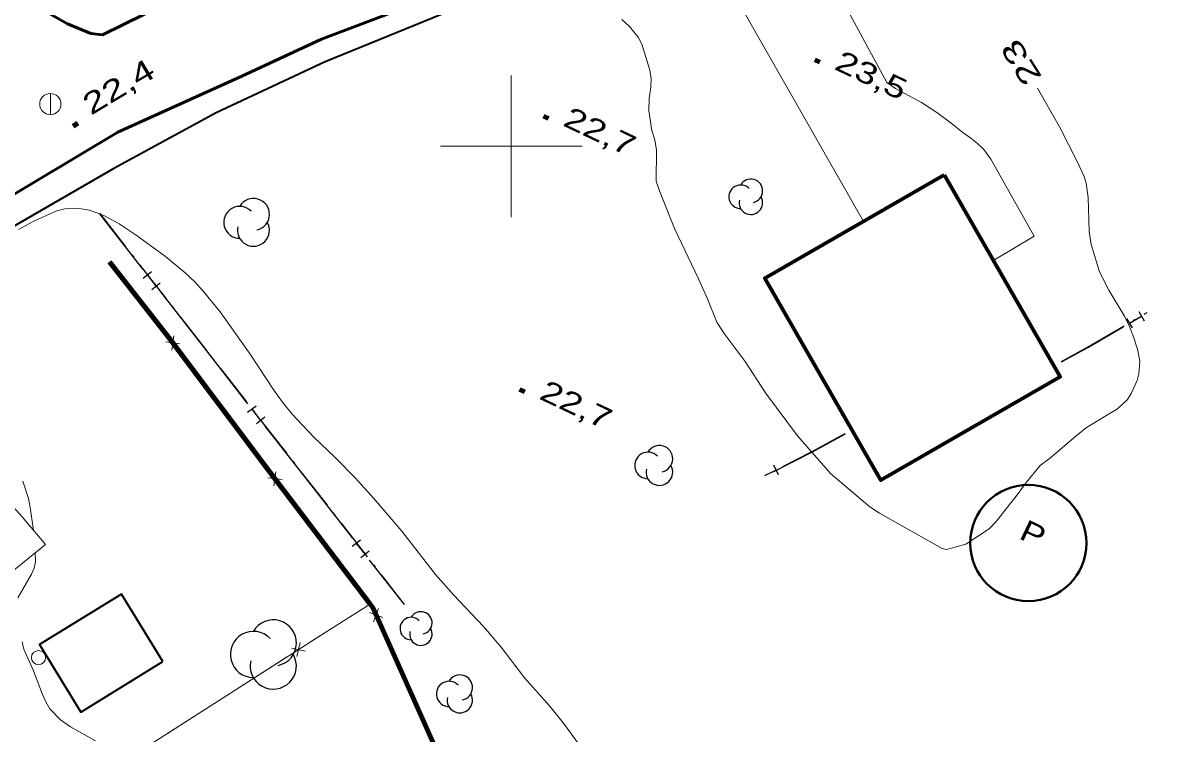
# Model space of a CAD drawing. Extents: x 356765 to 358572, y 5103174 to 5104650.
# Drawn here: x 357465.5 to 357547, y 5103858.5 to 5103908.7 of the extents above; entities that cross this region are included whole.
import ezdxf
from ezdxf.enums import TextEntityAlignment as Align

# ---------------------------------------------------------------- set-up
doc = ezdxf.new("R2010")
doc.units = 0
doc.header["$LTSCALE"] = 0.6
doc.linetypes.add('DOT_DASHED', pattern=[7.7, 5, -1.2, 0.3, -1.2])
for name, color, linetype, lineweight in [('19', 7, 'Continuous', 13), ('2', 7, 'Continuous', 13), ('21', 7, 'Continuous', 53), ('22', 7, 'Continuous', 35), ('3', 7, 'Continuous', 140), ('31', 7, 'Continuous', 70), ('36', 7, 'Continuous', 13), ('37', 7, 'Continuous', 13), ('38', 7, 'Continuous', 40), ('44', 7, 'Continuous', 25), ('61', 7, 'Continuous', 13)]:
    doc.layers.add(name, color=color, linetype=linetype, lineweight=lineweight)

msp = doc.modelspace()

# ---------------------------------------------------------------- linework, layer by layer
at = {"layer": '19'}
for p, q in [((357526.52, 5103904.49), (357519.66, 5103917.24)), ((357513.1, 5103915.34), (357524.85, 5103894.74))]:
    msp.add_line(p, q, dxfattribs=at)
for points in [[(357526.52, 5103904.49), (357527.12, 5103904.07), (357528.96, 5103903.09), (357530.04, 5103902.39), (357531.07, 5103901.62), (357531.89, 5103900.98), (357532.44, 5103900.57), (357532.92, 5103900.2), (357533.36, 5103899.77), (357533.87, 5103899.09), (357536.92, 5103893.64), (357534.13, 5103891.98)], [(357453.17, 5103887.5), (357465.48, 5103873.84), (357467.12, 5103871.87), (357464.62, 5103869.85), (357463.31, 5103871.23), (357454.95, 5103881.24), (357452.89, 5103883.17), (357451.37, 5103884.38), (357449.99, 5103885.55)]]:
    msp.add_lwpolyline(points, dxfattribs=at)
at = {"layer": '2'}
for points in [[(357507.82, 5103908.95), (357508.36, 5103908.45), (357508.96, 5103907.71), (357509.21, 5103907.21), (357509.79, 5103905.38), (357509.89, 5103904.78), (357509.86, 5103904.17), (357509.74, 5103903.37), (357509.71, 5103902.51), (357509.92, 5103901.12), (357510.13, 5103900.45), (357510.25, 5103899.73), (357510.24, 5103897.53), (357510.46, 5103896.84), (357511.53, 5103894.19), (357513.23, 5103890.63), (357513.83, 5103889.28), (357514.51, 5103887.58), (357515.03, 5103886.78), (357516.52, 5103884.79), (357517.96, 5103882.59), (357520.22, 5103879.55), (357522.57, 5103876.86), (357525.31, 5103874.54), (357526, 5103874.09), (357530.42, 5103871.59), (357530.74, 5103871.53), (357532.1, 5103871.91), (357533.74, 5103872.99), (357534.26, 5103873.53), (357535.73, 5103875.38), (357536.38, 5103876.29), (357537.34, 5103877.46), (357537.97, 5103877.93), (357539.85, 5103879.54), (357540.62, 5103880.13), (357542.8, 5103881.46), (357543.5, 5103882.12), (357543.76, 5103882.53), (357544.19, 5103883.47), (357544.31, 5103883.94), (357544.37, 5103884.83), (357544.21, 5103885.68), (357543.96, 5103886.47), (357543.66, 5103887.26), (357543.29, 5103888.01), (357542.2, 5103889.84), (357541.53, 5103891.12), (357540.95, 5103893.05), (357540.81, 5103893.98), (357540.74, 5103896.38), (357540.6, 5103897.38), (357540.44, 5103897.86), (357540, 5103898.83), (357538.69, 5103901.41), (357537.15, 5103904.11)], [(357505.79, 5103856.38), (357503.75, 5103859.17), (357502.71, 5103860.5), (357500.94, 5103862.46), (357499.28, 5103864.62), (357498.04, 5103866.09), (357495.95, 5103868.3), (357494.66, 5103869.76), (357492.27, 5103872.82), (357490.3, 5103875.12), (357488.99, 5103876.58), (357487.56, 5103878.03), (357486.04, 5103879.48), (357484.53, 5103881.08), (357483.84, 5103881.93), (357483.23, 5103882.78), (357481.62, 5103885.25), (357479.44, 5103888.3), (357478.25, 5103889.76), (357477.65, 5103890.43), (357476.99, 5103891.05), (357475.59, 5103892.22), (357473.53, 5103893.73), (357472.33, 5103894.53), (357471.29, 5103895.08), (357470.74, 5103895.3), (357470.19, 5103895.48), (357469.63, 5103895.58), (357469.07, 5103895.63), (357468.49, 5103895.59), (357467.93, 5103895.44), (357467.37, 5103895.21), (357466.25, 5103894.68), (357465.21, 5103894.12)], [(357465.51, 5103876.34), (357465.91, 5103875.13), (357466.04, 5103874.5), (357466.28, 5103872.88)], [(357466.4, 5103871.29), (357466.41, 5103870.65), (357466.31, 5103870.22), (357466.12, 5103869.78), (357465.16, 5103868.11)], [(357465.48, 5103865), (357465.6, 5103864.49), (357466.27, 5103862.96), (357466.9, 5103861.3), (357467.13, 5103860.78), (357467.42, 5103860.28), (357468.17, 5103859.51), (357468.88, 5103859.01), (357470.64, 5103858.01)]]:
    msp.add_lwpolyline(points, dxfattribs=at)
at = {"layer": '21'}
for points in [[(357471.14, 5103907.86), (357470.33, 5103907.97), (357468.68, 5103908.63), (357466.84, 5103909.68), (357464.76, 5103911.63), (357462.43, 5103913.84), (357445.34, 5103929.7), (357443.26, 5103931.71), (357439.31, 5103935.34), (357435.21, 5103939.42), (357431.12, 5103943.34), (357426.66, 5103947.84), (357421.28, 5103952.59), (357416.19, 5103957.55), (357411.47, 5103962.13), (357406.99, 5103966.4)], [(357651.76, 5103955.95), (357619.95, 5103948.59), (357588.58, 5103941.73), (357566.37, 5103936.76), (357548.68, 5103932.92), (357532.03, 5103928.56), (357530.85, 5103928.26), (357513.75, 5103924.04), (357511.54, 5103923.43), (357501.65, 5103920.72), (357490.41, 5103916.62), (357474.1, 5103909.32), (357471.14, 5103907.86)], [(357678.36, 5103954.94), (357640.5, 5103946.09), (357619.43, 5103941.41), (357599.16, 5103936.98), (357552.82, 5103926.37), (357536.94, 5103922.93), (357520.26, 5103918.95), (357503.82, 5103914.09), (357486.6, 5103907.55), (357480.97, 5103904.95), (357472.22, 5103900.99), (357457.26, 5103892.04), (357451.72, 5103889.03), (357438.42, 5103880.3), (357419.6, 5103867.79), (357409.99, 5103860.91), (357402.64, 5103855.12), (357395.85, 5103849.3), (357387.1, 5103841.32), (357379.78, 5103834.37), (357370.08, 5103824.18), (357363.77, 5103817.05), (357355.31, 5103807.73), (357353.75, 5103805.99)]]:
    msp.add_lwpolyline(points, dxfattribs=at)
at = {"layer": '22'}
msp.add_lwpolyline([(357647.75, 5103946.51), (357634.21, 5103943.46), (357622.47, 5103940.88), (357609.15, 5103938.01), (357596.04, 5103935), (357584.77, 5103932.34), (357572.98, 5103929.8), (357562.05, 5103927.46), (357547.85, 5103924.19), (357536.87, 5103921.73), (357525.36, 5103918.83), (357514.86, 5103915.9), (357504.84, 5103912.75), (357495.77, 5103909.59), (357486.87, 5103905.97), (357479.16, 5103902.36), (357471.94, 5103898.43), (357462.55, 5103893.01), (357451.44, 5103886.54), (357441.53, 5103880.61), (357430.12, 5103873.12), (357417.36, 5103864.38), (357407.44, 5103856.91)], dxfattribs=at)
at = {"layer": '3'}
for p, q in [((357521.43, 5103906.1), (357521.79, 5103905.93)), ((357502.27, 5103902.12), (357502.63, 5103901.95)), ((357469.06, 5103901.41), (357469.4, 5103901.62)), ((357500.59, 5103882.83), (357500.95, 5103882.66))]:
    msp.add_line(p, q, dxfattribs=at)
at = {"layer": '31'}
msp.add_lwpolyline([(357530.57, 5103897.97), (357538.76, 5103883.71), (357526.09, 5103876.43), (357517.9, 5103890.69), (357530.57, 5103897.97)], close=True, dxfattribs=at)
at = {"layer": '31', "lineweight": 35}
msp.add_lwpolyline([(357475.41, 5103863.62), (357472.49, 5103868.38), (357466.7, 5103864.82), (357469.62, 5103860.05), (357475.41, 5103863.62)], close=True, dxfattribs=at)
at = {"layer": '36'}
msp.add_line((357467.46, 5103902.21), (357467.46, 5103903.71), dxfattribs=at)
for centre, radius in [((357467.4575, 5103902.9723), 0.75), ((357466.6238, 5103863.8971), 0.5)]:
    msp.add_circle(centre, radius, dxfattribs=at)
at = {"layer": '37', "lineweight": 25}
for p, q in [((357470.93, 5103895.23), (357474, 5103891.29)), ((357474.61, 5103891.12), (357474.02, 5103890.66)), ((357474.31, 5103890.89), (357474.93, 5103890.1)), ((357475.22, 5103890.33), (357474.63, 5103889.87)), ((357475.23, 5103889.71), (357478.31, 5103885.76)), ((357543.64, 5103887.51), (357544.5, 5103888.01)), ((357544.31, 5103888.33), (357544.69, 5103887.68)), ((357543.45, 5103887.83), (357543.83, 5103887.18)), ((357478.31, 5103885.76), (357481.38, 5103881.82)), ((357481.98, 5103881.65), (357481.39, 5103881.19)), ((357481.69, 5103881.43), (357482.3, 5103880.64)), ((357482.6, 5103880.86), (357482.01, 5103880.4)), ((357482.61, 5103880.24), (357485.68, 5103876.3)), ((357518.87, 5103876.8), (357518.53, 5103877.47)), ((357518.7, 5103877.13), (357517.89, 5103876.72)), ((357485.68, 5103876.3), (357488.76, 5103872.36)), ((357489.36, 5103872.19), (357488.77, 5103871.73)), ((357489.06, 5103871.96), (357489.68, 5103871.17)), ((357489.98, 5103871.4), (357489.38, 5103870.94)), ((357489.98, 5103870.78), (357492.43, 5103867.64))]:
    msp.add_line(p, q, dxfattribs=at)
at = {"layer": '37', "linetype": 'DOT_DASHED', "lineweight": 25}
msp.add_line((357470.95, 5103895.24), (357492.45, 5103867.65), dxfattribs=at)
at = {"layer": '37'}
for p, q in [((357472.42, 5103890.85), (357471.64, 5103891.84)), ((357475.49, 5103886.9), (357472.42, 5103890.85)), ((357476.17, 5103886.61), (357476.03, 5103885.61)), ((357476.6, 5103886.04), (357475.61, 5103886.18)), ((357479.71, 5103881.32), (357476.7, 5103885.31)), ((357482.72, 5103877.32), (357479.71, 5103881.32)), ((357483.82, 5103876.46), (357482.82, 5103876.59)), ((357483.39, 5103877.02), (357483.25, 5103876.03)), ((357486.95, 5103871.75), (357483.92, 5103875.73)), ((357489.98, 5103867.77), (357486.95, 5103871.75)), ((357490.93, 5103866.72), (357489.99, 5103867.08)), ((357490.64, 5103867.37), (357490.28, 5103866.43)), ((357492.9, 5103861.42), (357490.87, 5103865.99)), ((357484.49, 5103864.57), (357485.47, 5103864.35)), ((357485.09, 5103864.95), (357484.87, 5103863.97)), ((357484.14, 5103863.92), (357479.93, 5103861.22)), ((357479.93, 5103861.22), (357475.72, 5103858.53)), ((357494.94, 5103856.85), (357492.9, 5103861.42))]:
    msp.add_line(p, q, dxfattribs=at)
at = {"layer": '37', "lineweight": 158}
msp.add_lwpolyline([(357503.69, 5103836.77), (357493.61, 5103831.68), (357488.95, 5103831.74), (357488.76, 5103840.5), (357489.78, 5103844.61), (357494.83, 5103851.53), (357495.47, 5103855.66), (357490.22, 5103867.44), (357490.05, 5103867.67), (357482.98, 5103876.97), (357475.8, 5103886.51), (357471.64, 5103891.84)], dxfattribs=at)
at = {"layer": '37', "linetype": 'DOT_DASHED', "lineweight": 25}
for points in [[(357538.85, 5103884.8), (357540.69, 5103885.82), (357544.89, 5103888.26)], [(357523.57, 5103879.68), (357521.19, 5103878.38), (357517.9, 5103876.7)]]:
    msp.add_lwpolyline(points, dxfattribs=at)
at = {"layer": '37', "lineweight": 25}
for points in [[(357538.86, 5103884.78), (357540.7, 5103885.8), (357543.2, 5103887.25)], [(357523.56, 5103879.7), (357521.18, 5103878.4), (357519.14, 5103877.36)]]:
    msp.add_lwpolyline(points, dxfattribs=at)
at = {"layer": '37'}
for points in [[(357490.05, 5103867.67), (357487.25, 5103865.91), (357468.88, 5103854.15), (357465.17, 5103851.55), (357442.27, 5103836.44)], [(357490.05, 5103867.67), (357487.25, 5103865.91), (357485.82, 5103865)]]:
    msp.add_lwpolyline(points, dxfattribs=at)
at = {"layer": '38'}
msp.add_circle((357536.51, 5103871.9803), 4.1015, dxfattribs=at)
at = {"layer": '44'}
for centre, radius, start, end in [((357516.2015, 5103896.4289), 0.833, 44.11537, 269.80396), ((357516.9179, 5103896.8454), 0.833, 282.26917, 149.72626), ((357481.8003, 5103895.1886), 1.1261, 282.26917, 149.72626), ((357516.9179, 5103896.0124), 0.833, 166.93686, 29.62122), ((357480.8319, 5103894.6256), 1.1261, 44.11537, 269.80396), ((357481.8003, 5103894.0625), 1.1261, 166.93686, 29.62122), ((357509.655, 5103877.4613), 0.9382, 44.11537, 269.80396), ((357510.4618, 5103877.9304), 0.9382, 282.26917, 149.72626), ((357510.4618, 5103876.9922), 0.9382, 166.93686, 29.62122), ((357493.6211, 5103866.3444), 0.7928, 282.26917, 149.72626), ((357483.2009, 5103864.9322), 1.6303, 282.26917, 149.72626), ((357492.9393, 5103865.948), 0.7928, 44.11537, 269.80396), ((357481.7989, 5103864.117), 1.6303, 44.11537, 269.80396), ((357493.6211, 5103865.5516), 0.7928, 166.93686, 29.62122), ((357483.2009, 5103863.3019), 1.6303, 166.93686, 29.62122), ((357495.6051, 5103861.3303), 0.8929, 44.11537, 269.80396), ((357496.3729, 5103861.7767), 0.8929, 282.26917, 149.72626), ((357496.3729, 5103860.8838), 0.8929, 166.93686, 29.62122)]:
    msp.add_arc(centre, radius, start, end, dxfattribs=at)
at = {"layer": '61'}
for p, q in [((357500, 5103895), (357500, 5103905)), ((357495, 5103900), (357505, 5103900))]:
    msp.add_line(p, q, dxfattribs=at)

# ---------------------------------------------------------------- texts
at = {"layer": '2', "width": 1.5}
msp.add_text('23', height=1.5, rotation=122.147, dxfattribs=at).set_placement((357536.6244, 5103906.301), align=Align.CENTER)
at = {"layer": '3'}
for s, rotation, width, p in [('22,4   ', 31.014, 1.4, (357470.32, 5103902.15)), ('23,5   ', 334.619, 1.35, (357522.73, 5103905.47)), ('22,7   ', 334.619, 1.35, (357503.57, 5103901.49)), ('22,7   ', 334.619, 1.35, (357501.89, 5103882.2))]:
    msp.add_text(s, height=1.5, rotation=rotation, dxfattribs=dict(at, width=width)).set_placement(p)
at = {"layer": '38', "width": 1.25}
msp.add_text('P', height=1.5, rotation=334.69, dxfattribs=at).set_placement((357535.77, 5103872.33))

doc.saveas('drawing.dxf')
